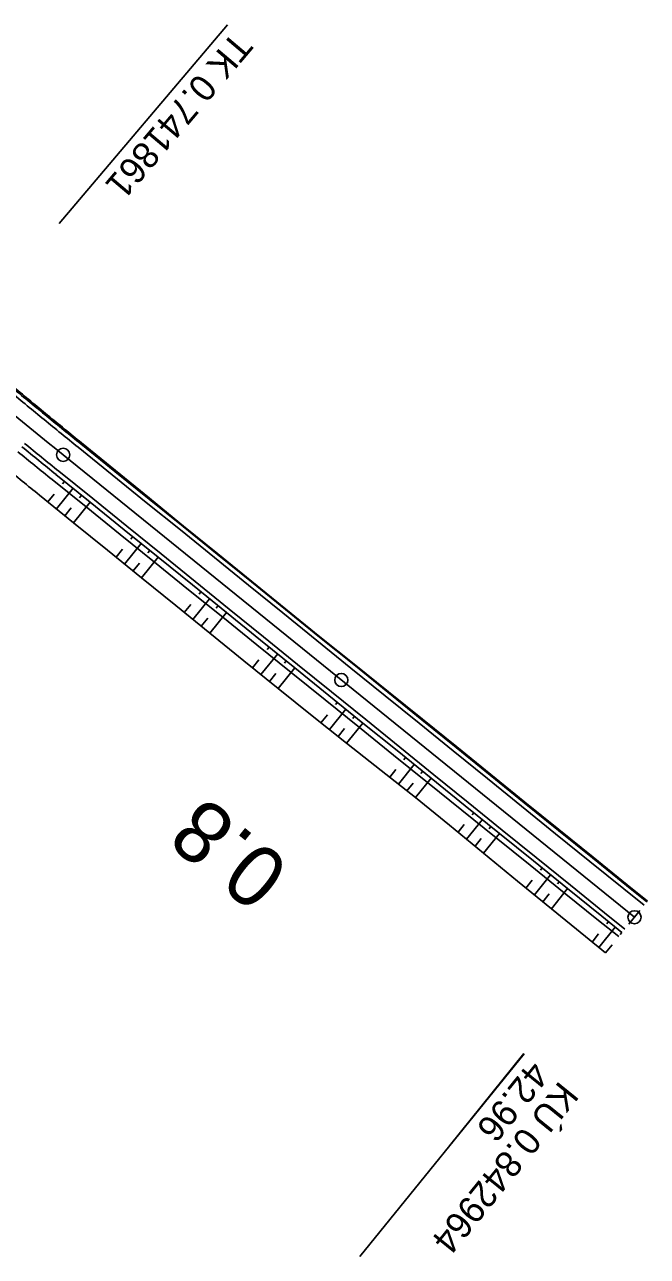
# Model space of a CAD drawing. Extents: x -481645 to -478728, y -1113199 to -1110710.
# Drawn here: x -481173.6 to -481102.7, y -1113199.2 to -1113058.9 of the extents above; entities that cross this region are included whole.
import ezdxf

# ---------------------------------------------------------------- set-up
doc = ezdxf.new("R2010")
doc.units = 0
for name, color, linetype in [('Vrstva 41', 7, 'Continuous'), ('Vrstva 42', 7, 'Continuous'), ('Vrstva 43', 7, 'Continuous'), ('Vrstva 44', 7, 'Continuous'), ('Vrstva 45', 7, 'Continuous'), ('Vrstva 46', 7, 'Continuous'), ('Vrstva 47', 7, 'Continuous'), ('Vrstva 48', 7, 'Continuous'), ('Vrstva 49', 7, 'Continuous'), ('Vrstva 50', 7, 'Continuous'), ('Vrstva 51', 7, 'Continuous')]:
    doc.layers.add(name, color=color, linetype=linetype)

msp = doc.modelspace()

# ---------------------------------------------------------------- linework, layer by layer
at = {"layer": 'Vrstva 41'}
msp.add_line((-481169.23, -1113107.87), (-481104.14, -1113160.55), dxfattribs=at)
msp.add_arc((-480665.96, -1112486.01), 800, 229.77294, 231.01682, dxfattribs=at)
at = {"layer": 'Vrstva 42'}
for p, q in [((-481167.13, -1113106.51), (-481163.26, -1113109.67)), ((-481163.26, -1113109.67), (-481159.38, -1113112.82)), ((-481171.94, -1113112.45), (-481168.06, -1113115.6)), ((-481159.38, -1113112.82), (-481155.5, -1113115.98)), ((-481168.06, -1113115.6), (-481164.17, -1113118.74)), ((-481155.5, -1113115.98), (-481151.62, -1113119.13)), ((-481164.17, -1113118.74), (-481160.29, -1113121.89)), ((-481151.62, -1113119.13), (-481147.74, -1113122.29)), ((-481160.29, -1113121.89), (-481156.4, -1113125.04)), ((-481147.74, -1113122.29), (-481143.86, -1113125.44)), ((-481156.4, -1113125.04), (-481152.51, -1113128.18)), ((-481143.86, -1113125.44), (-481139.98, -1113128.59)), ((-481152.51, -1113128.18), (-481148.63, -1113131.33)), ((-481139.98, -1113128.59), (-481136.08, -1113131.72)), ((-481148.63, -1113131.33), (-481144.74, -1113134.48)), ((-481136.08, -1113131.72), (-481132.18, -1113134.85)), ((-481144.74, -1113134.48), (-481140.85, -1113137.61)), ((-481132.18, -1113134.85), (-481128.28, -1113137.98)), ((-481140.85, -1113137.61), (-481136.93, -1113140.72)), ((-481128.28, -1113137.98), (-481124.39, -1113141.12)), ((-481136.93, -1113140.72), (-481133, -1113143.82)), ((-481124.39, -1113141.12), (-481120.51, -1113144.27)), ((-481133, -1113143.82), (-481129.08, -1113146.92)), ((-481120.51, -1113144.27), (-481116.63, -1113147.43)), ((-481129.08, -1113146.92), (-481125.2, -1113150.07)), ((-481116.63, -1113147.43), (-481112.74, -1113150.57)), ((-481125.2, -1113150.07), (-481121.34, -1113153.25)), ((-481112.74, -1113150.57), (-481108.86, -1113153.72)), ((-481121.34, -1113153.25), (-481117.48, -1113156.42)), ((-481108.86, -1113153.72), (-481104.97, -1113156.87)), ((-481117.48, -1113156.42), (-481113.61, -1113159.6)), ((-481104.97, -1113156.87), (-481102.67, -1113158.73)), ((-481113.61, -1113159.6), (-481109.73, -1113162.75)), ((-481109.73, -1113162.75), (-481107.43, -1113164.61))]:
    msp.add_line(p, q, dxfattribs=at)
for centre, radius, start, end in [((-480663.63, -1112487.93), 797.6, 230.13918, 230.49729), ((-481421.48, -1113413.68), 398.8, 50.3738, 51.0904), ((-480919.6, -1112798.7), 402.63, 230.4755, 231.191)]:
    msp.add_arc(centre, radius, start, end, dxfattribs=at)
at = {"layer": 'Vrstva 43'}
for p, q in [((-481170.5, -1113110.67), (-481166.61, -1113113.81)), ((-481166.61, -1113113.81), (-481162.72, -1113116.95)), ((-481162.72, -1113116.95), (-481158.83, -1113120.09)), ((-481158.83, -1113120.09), (-481154.94, -1113123.23)), ((-481154.94, -1113123.23), (-481151.04, -1113126.37)), ((-481151.04, -1113126.37), (-481147.15, -1113129.51)), ((-481147.15, -1113129.51), (-481143.26, -1113132.65)), ((-481143.26, -1113132.65), (-481139.37, -1113135.79)), ((-481139.37, -1113135.79), (-481135.48, -1113138.93)), ((-481135.48, -1113138.93), (-481131.59, -1113142.07)), ((-481131.59, -1113142.07), (-481127.7, -1113145.21)), ((-481127.7, -1113145.21), (-481123.8, -1113148.34)), ((-481123.8, -1113148.34), (-481119.91, -1113151.49)), ((-481119.91, -1113151.49), (-481116.02, -1113154.62)), ((-481116.02, -1113154.62), (-481112.13, -1113157.76)), ((-481112.13, -1113157.76), (-481108.24, -1113160.9)), ((-481108.24, -1113160.9), (-481105.93, -1113162.76))]:
    msp.add_line(p, q, dxfattribs=at)
msp.add_arc((-480919.65, -1112797.19), 401.49, 230.6175, 231.3333, dxfattribs=at)
at = {"layer": 'Vrstva 44'}
for p, q in [((-481167.22, -1113106.61), (-481163.33, -1113109.76)), ((-481170.05, -1113110.11), (-481166.16, -1113113.25)), ((-481163.33, -1113109.76), (-481159.44, -1113112.9)), ((-481159.44, -1113112.9), (-481155.55, -1113116.04)), ((-481166.16, -1113113.25), (-481162.27, -1113116.4)), ((-481162.27, -1113116.4), (-481158.39, -1113119.54)), ((-481155.55, -1113116.04), (-481151.67, -1113119.19)), ((-481158.39, -1113119.54), (-481154.5, -1113122.69)), ((-481151.67, -1113119.19), (-481147.78, -1113122.34)), ((-481154.5, -1113122.69), (-481150.61, -1113125.83)), ((-481147.78, -1113122.34), (-481143.9, -1113125.48)), ((-481143.9, -1113125.48), (-481140.01, -1113128.63)), ((-481150.61, -1113125.83), (-481146.73, -1113128.98)), ((-481146.73, -1113128.98), (-481142.84, -1113132.12)), ((-481140.01, -1113128.63), (-481136.12, -1113131.77)), ((-481142.84, -1113132.12), (-481138.95, -1113135.27)), ((-481136.12, -1113131.77), (-481132.23, -1113134.92)), ((-481138.95, -1113135.27), (-481135.07, -1113138.42)), ((-481132.23, -1113134.92), (-481128.35, -1113138.06)), ((-481128.35, -1113138.06), (-481124.46, -1113141.21)), ((-481135.07, -1113138.42), (-481131.18, -1113141.56)), ((-481131.18, -1113141.56), (-481127.29, -1113144.71)), ((-481124.46, -1113141.21), (-481120.58, -1113144.35)), ((-481127.29, -1113144.71), (-481123.41, -1113147.85)), ((-481120.58, -1113144.35), (-481116.69, -1113147.5)), ((-481123.41, -1113147.85), (-481119.52, -1113151)), ((-481116.69, -1113147.5), (-481112.8, -1113150.65)), ((-481112.8, -1113150.65), (-481108.92, -1113153.79)), ((-481119.52, -1113151), (-481115.63, -1113154.14)), ((-481115.63, -1113154.14), (-481111.75, -1113157.29)), ((-481108.92, -1113153.79), (-481105.03, -1113156.94)), ((-481111.75, -1113157.29), (-481107.86, -1113160.43)), ((-481105.03, -1113156.94), (-481102.73, -1113158.8)), ((-481107.86, -1113160.43), (-481105.56, -1113162.3))]:
    msp.add_line(p, q, dxfattribs=at)
for centre, radius, start, end in [((-480665.96, -1112486.01), 797.75, 230.35582, 230.71392), ((-480917.53, -1112795.55), 398.88, 230.5305, 231.247), ((-480918.95, -1112797.29), 401.12, 230.5307, 231.2466)]:
    msp.add_arc(centre, radius, start, end, dxfattribs=at)
at = {"layer": 'Vrstva 45'}
for p, q in [((-481167.53, -1113107), (-481163.64, -1113110.14)), ((-481169.73, -1113109.72), (-481165.85, -1113112.86)), ((-481163.64, -1113110.14), (-481159.76, -1113113.29)), ((-481165.85, -1113112.86), (-481161.96, -1113116.01)), ((-481159.76, -1113113.29), (-481155.87, -1113116.43)), ((-481161.96, -1113116.01), (-481158.07, -1113119.16)), ((-481155.87, -1113116.43), (-481151.98, -1113119.58)), ((-481158.07, -1113119.16), (-481154.18, -1113122.3)), ((-481151.98, -1113119.58), (-481148.1, -1113122.73)), ((-481154.18, -1113122.3), (-481150.3, -1113125.45)), ((-481148.1, -1113122.73), (-481144.21, -1113125.87)), ((-481150.3, -1113125.45), (-481146.41, -1113128.59)), ((-481144.21, -1113125.87), (-481140.32, -1113129.02)), ((-481146.41, -1113128.59), (-481142.53, -1113131.74)), ((-481140.32, -1113129.02), (-481136.44, -1113132.16)), ((-481142.53, -1113131.74), (-481138.64, -1113134.88)), ((-481136.44, -1113132.16), (-481132.55, -1113135.31)), ((-481138.64, -1113134.88), (-481134.75, -1113138.03)), ((-481132.55, -1113135.31), (-481128.66, -1113138.45)), ((-481134.75, -1113138.03), (-481130.86, -1113141.17)), ((-481128.66, -1113138.45), (-481124.78, -1113141.6)), ((-481130.86, -1113141.17), (-481126.98, -1113144.32)), ((-481124.78, -1113141.6), (-481120.89, -1113144.74)), ((-481126.98, -1113144.32), (-481123.09, -1113147.46)), ((-481120.89, -1113144.74), (-481117, -1113147.89)), ((-481123.09, -1113147.46), (-481119.21, -1113150.61)), ((-481117, -1113147.89), (-481113.12, -1113151.03)), ((-481119.21, -1113150.61), (-481115.32, -1113153.76)), ((-481113.12, -1113151.03), (-481109.23, -1113154.18)), ((-481115.32, -1113153.76), (-481111.43, -1113156.9)), ((-481109.23, -1113154.18), (-481105.34, -1113157.32)), ((-481111.43, -1113156.9), (-481107.54, -1113160.05)), ((-481105.34, -1113157.32), (-481103.04, -1113159.19)), ((-481107.54, -1113160.05), (-481105.24, -1113161.91))]:
    msp.add_line(p, q, dxfattribs=at)
for centre, radius, start, end in [((-480665.96, -1112486.01), 798.25, 230.35582, 230.71392), ((-480917.69, -1112795.74), 399.12, 230.5305, 231.247), ((-480918.8, -1112797.1), 400.88, 230.5307, 231.2466)]:
    msp.add_arc(centre, radius, start, end, dxfattribs=at)
at = {"layer": 'Vrstva 46'}
for p, q in [((-481167.53, -1113107), (-481163.64, -1113110.14)), ((-481169.73, -1113109.72), (-481165.85, -1113112.86)), ((-481163.64, -1113110.14), (-481159.76, -1113113.29)), ((-481165.85, -1113112.86), (-481161.96, -1113116.01)), ((-481159.76, -1113113.29), (-481155.87, -1113116.43)), ((-481161.96, -1113116.01), (-481158.07, -1113119.16)), ((-481155.87, -1113116.43), (-481151.98, -1113119.58)), ((-481158.07, -1113119.16), (-481154.18, -1113122.3)), ((-481151.98, -1113119.58), (-481148.1, -1113122.73)), ((-481154.18, -1113122.3), (-481150.3, -1113125.45)), ((-481148.1, -1113122.73), (-481144.21, -1113125.87)), ((-481150.3, -1113125.45), (-481146.41, -1113128.59)), ((-481144.21, -1113125.87), (-481140.32, -1113129.02)), ((-481146.41, -1113128.59), (-481142.53, -1113131.74)), ((-481140.32, -1113129.02), (-481136.44, -1113132.16)), ((-481142.53, -1113131.74), (-481138.64, -1113134.88)), ((-481136.44, -1113132.16), (-481132.55, -1113135.31)), ((-481138.64, -1113134.88), (-481134.75, -1113138.03)), ((-481132.55, -1113135.31), (-481128.66, -1113138.45)), ((-481134.75, -1113138.03), (-481130.86, -1113141.17)), ((-481128.66, -1113138.45), (-481124.78, -1113141.6)), ((-481130.86, -1113141.17), (-481126.98, -1113144.32)), ((-481124.78, -1113141.6), (-481120.89, -1113144.74)), ((-481126.98, -1113144.32), (-481123.09, -1113147.46)), ((-481120.89, -1113144.74), (-481117, -1113147.89)), ((-481123.09, -1113147.46), (-481119.21, -1113150.61)), ((-481117, -1113147.89), (-481113.12, -1113151.03)), ((-481119.21, -1113150.61), (-481115.32, -1113153.76)), ((-481113.12, -1113151.03), (-481109.23, -1113154.18)), ((-481115.32, -1113153.76), (-481111.43, -1113156.9)), ((-481109.23, -1113154.18), (-481105.34, -1113157.32)), ((-481111.43, -1113156.9), (-481107.54, -1113160.05)), ((-481105.34, -1113157.32), (-481103.04, -1113159.19)), ((-481107.54, -1113160.05), (-481105.24, -1113161.91))]:
    msp.add_line(p, q, dxfattribs=at)
for centre, radius, start, end in [((-480665.96, -1112486.01), 798.25, 230.35582, 230.71392), ((-480917.69, -1112795.74), 399.12, 230.5305, 231.247), ((-480918.8, -1112797.1), 400.88, 230.5307, 231.2466)]:
    msp.add_arc(centre, radius, start, end, dxfattribs=at)
at = {"layer": 'Vrstva 47'}
for p, q in [((-481104.77, -1113161.32), (-481103.51, -1113159.77)), ((-481116.73, -1113176.09), (-481125.22, -1113186.59))]:
    msp.add_line(p, q, dxfattribs=at)
at = {"layer": 'Vrstva 48'}
for p, q in [((-481150.51, -1113058.86), (-481169.69, -1113081.53)), ((-481116.72, -1113176.1), (-481135.41, -1113199.18))]:
    msp.add_line(p, q, dxfattribs=at)
for centre in [(-481169.23, -1113107.87), (-481104.14, -1113160.55)]:
    msp.add_circle(centre, 0.75, dxfattribs=at)
at = {"layer": 'Vrstva 49'}
msp.add_circle((-481137.54, -1113133.52), 0.75, dxfattribs=at)
at = {"layer": 'Vrstva 50'}
for p, q in [((-481173.01, -1113101.88), (-481172.92, -1113101.76)), ((-481172.05, -1113102.67), (-481172, -1113102.61)), ((-481171.96, -1113102.56), (-481171.96, -1113102.56)), ((-481171.09, -1113103.46), (-481170.99, -1113103.35)), ((-481166.24, -1113107.4), (-481166.2, -1113107.35)), ((-481166.16, -1113107.3), (-481166.16, -1113107.3)), ((-481165.27, -1113108.18), (-481165.2, -1113108.09)), ((-481164.3, -1113108.97), (-481164.26, -1113108.92)), ((-481164.23, -1113108.88), (-481164.23, -1113108.88)), ((-481163.33, -1113109.76), (-481163.26, -1113109.67)), ((-481158.47, -1113113.69), (-481158.44, -1113113.65)), ((-481158.41, -1113113.61), (-481158.41, -1113113.61)), ((-481157.5, -1113114.47), (-481157.44, -1113114.4)), ((-481156.53, -1113115.26), (-481156.5, -1113115.22)), ((-481156.47, -1113115.19), (-481156.47, -1113115.19)), ((-481155.55, -1113116.04), (-481155.5, -1113115.98)), ((-481150.7, -1113119.98), (-481150.67, -1113119.95)), ((-481150.65, -1113119.92), (-481150.65, -1113119.92)), ((-481149.73, -1113120.76), (-481149.68, -1113120.71)), ((-481148.75, -1113121.55), (-481148.73, -1113121.52)), ((-481148.71, -1113121.5), (-481148.71, -1113121.5)), ((-481147.78, -1113122.34), (-481147.74, -1113122.29)), ((-481142.92, -1113126.27), (-481142.91, -1113126.25)), ((-481142.89, -1113126.23), (-481142.89, -1113126.23)), ((-481141.95, -1113127.05), (-481141.92, -1113127.02)), ((-481140.98, -1113127.84), (-481140.97, -1113127.82)), ((-481140.95, -1113127.8), (-481140.95, -1113127.8)), ((-481140.01, -1113128.63), (-481139.98, -1113128.59)), ((-481135.15, -1113132.56), (-481135.13, -1113132.53)), ((-481135.1, -1113132.5), (-481135.1, -1113132.5)), ((-481134.18, -1113133.35), (-481134.13, -1113133.28)), ((-481133.21, -1113134.13), (-481133.18, -1113134.1)), ((-481133.15, -1113134.07), (-481133.15, -1113134.07)), ((-481132.23, -1113134.92), (-481132.18, -1113134.85)), ((-481127.38, -1113138.85), (-481127.34, -1113138.81)), ((-481127.31, -1113138.77), (-481127.31, -1113138.77)), ((-481126.41, -1113139.64), (-481126.34, -1113139.55)), ((-481125.43, -1113140.42), (-481125.4, -1113140.38)), ((-481125.36, -1113140.33), (-481125.36, -1113140.33)), ((-481124.46, -1113141.21), (-481124.39, -1113141.12)), ((-481119.6, -1113145.14), (-481119.57, -1113145.1)), ((-481119.54, -1113145.06), (-481119.54, -1113145.06)), ((-481118.63, -1113145.93), (-481118.57, -1113145.85)), ((-481117.66, -1113146.71), (-481117.63, -1113146.68)), ((-481117.6, -1113146.64), (-481117.6, -1113146.64)), ((-481116.69, -1113147.5), (-481116.63, -1113147.43)), ((-481111.83, -1113151.43), (-481111.8, -1113151.4)), ((-481111.77, -1113151.36), (-481111.77, -1113151.36)), ((-481110.86, -1113152.22), (-481110.8, -1113152.15)), ((-481109.89, -1113153.01), (-481109.86, -1113152.97)), ((-481109.83, -1113152.94), (-481109.83, -1113152.94)), ((-481108.92, -1113153.79), (-481108.86, -1113153.72)), ((-481104.26, -1113157.56), (-481104.23, -1113157.52)), ((-481104.21, -1113157.49), (-481104.21, -1113157.49)), ((-481103.49, -1113158.18), (-481103.44, -1113158.11)), ((-481102.73, -1113158.8), (-481102.7, -1113158.76)), ((-481102.67, -1113158.73), (-481102.67, -1113158.73))]:
    msp.add_line(p, q, dxfattribs=at)
at = {"layer": 'Vrstva 51'}
for p, q in [((-481169.07, -1113110.89), (-481169.3, -1113111.17)), ((-481170.25, -1113112.35), (-481170.97, -1113113.24)), ((-481168.1, -1113111.68), (-481170, -1113114.02)), ((-481167.13, -1113112.47), (-481167.36, -1113112.75)), ((-481168.3, -1113113.92), (-481169.03, -1113114.81)), ((-481166.16, -1113113.25), (-481168.06, -1113115.6)), ((-481161.3, -1113117.18), (-481161.52, -1113117.46)), ((-481162.47, -1113118.63), (-481163.2, -1113119.53)), ((-481160.33, -1113117.97), (-481162.23, -1113120.32)), ((-481158.39, -1113119.54), (-481160.29, -1113121.89)), ((-481159.36, -1113118.76), (-481159.58, -1113119.03)), ((-481160.53, -1113120.2), (-481161.26, -1113121.1)), ((-481152.56, -1113124.26), (-481154.46, -1113126.61)), ((-481153.53, -1113123.48), (-481153.74, -1113123.74)), ((-481154.7, -1113124.92), (-481155.43, -1113125.82)), ((-481151.58, -1113125.05), (-481151.8, -1113125.32)), ((-481152.75, -1113126.49), (-481153.49, -1113127.4)), ((-481150.61, -1113125.83), (-481152.51, -1113128.18)), ((-481145.75, -1113129.77), (-481145.97, -1113130.03)), ((-481146.92, -1113131.21), (-481147.66, -1113132.12)), ((-481144.78, -1113130.55), (-481146.69, -1113132.91)), ((-481142.84, -1113132.12), (-481144.74, -1113134.48)), ((-481143.81, -1113131.34), (-481144.02, -1113131.6)), ((-481144.98, -1113132.78), (-481145.72, -1113133.69)), ((-481137.01, -1113136.84), (-481138.89, -1113139.16)), ((-481137.98, -1113136.06), (-481138.19, -1113136.31)), ((-481139.13, -1113137.48), (-481139.87, -1113138.39)), ((-481136.04, -1113137.63), (-481136.24, -1113137.89)), ((-481137.18, -1113139.04), (-481137.91, -1113139.94)), ((-481135.07, -1113138.42), (-481136.93, -1113140.72)), ((-481130.21, -1113142.35), (-481130.41, -1113142.6)), ((-481131.32, -1113143.72), (-481132.02, -1113144.59)), ((-481129.24, -1113143.13), (-481131.04, -1113145.37)), ((-481128.26, -1113143.92), (-481128.47, -1113144.17)), ((-481129.37, -1113145.28), (-481130.06, -1113146.14)), ((-481127.29, -1113144.71), (-481129.08, -1113146.92)), ((-481121.46, -1113149.43), (-481123.27, -1113151.66)), ((-481122.43, -1113148.64), (-481122.63, -1113148.88)), ((-481123.53, -1113150), (-481124.23, -1113150.86)), ((-481120.49, -1113150.21), (-481120.69, -1113150.46)), ((-481121.59, -1113151.58), (-481122.3, -1113152.45)), ((-481119.52, -1113151), (-481121.34, -1113153.25)), ((-481114.66, -1113154.93), (-481114.85, -1113155.17)), ((-481115.78, -1113156.31), (-481116.51, -1113157.22)), ((-481113.69, -1113155.72), (-481115.54, -1113158.01)), ((-481112.72, -1113156.5), (-481112.91, -1113156.74)), ((-481113.84, -1113157.89), (-481114.58, -1113158.8)), ((-481111.75, -1113157.29), (-481113.61, -1113159.6)), ((-481106.33, -1113161.68), (-481108.2, -1113163.99)), ((-481107.09, -1113161.05), (-481107.28, -1113161.29)), ((-481108.22, -1113162.45), (-481108.97, -1113163.37)), ((-481105.56, -1113162.3), (-481105.75, -1113162.53)), ((-481106.68, -1113163.69), (-481107.43, -1113164.61))]:
    msp.add_line(p, q, dxfattribs=at)

# ---------------------------------------------------------------- texts
at = {"layer": 'Vrstva 47'}
msp.add_text('42.96', height=2.999, rotation=231.0168, dxfattribs=at).set_placement((-481115.95, -1113176.72))
at = {"layer": 'Vrstva 48'}
for s, rotation, p in [('TK 0.741861', 229.7729, (-481149.75, -1113059.5)), ('KÚ 0.842964', 231.0168, (-481112.65, -1113179.08))]:
    msp.add_text(s, height=2.999, rotation=rotation, dxfattribs=at).set_placement(p)
at = {"layer": 'Vrstva 49'}
msp.add_text('0.8', height=7, rotation=140.9712, dxfattribs=at).set_placement((-481143.1, -1113154.76))

doc.saveas('drawing.dxf')
